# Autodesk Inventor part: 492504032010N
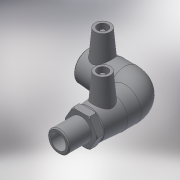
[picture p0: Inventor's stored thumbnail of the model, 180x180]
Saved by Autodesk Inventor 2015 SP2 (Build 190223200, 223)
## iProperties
Created: 2017-06
Part Number: 492504032010N
Material: Generic
Description: PLASSON 90° ELBOW MALE TRANSITION 32 x 1"
Document SubType Name: Modeling
Designer: KIM
Mass: 133.588 g
Surface Area: 417.209 cm^2
Volume: 133.588 cm^3
Density: 1 g/cm^3
Appearance: Default
Author: KIM
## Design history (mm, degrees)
derived "492504.ipt"
feature "Solid1::492504.ipt"
tag "TaggingFeature1"
body "Solid1"
other parameters: "d2" = 44, "d4" = 28, "d5" = 39.6, "d8" = 168 deg, "d10" = 17.6, "d11" = 5.86667, "d29" = 42, "d30" = 15, "d31" = 46.2, "d34" = 5 deg, "d41" = 4, "d42" = 14, "d43" = 0, "d48" = 62, "d49" = 32, "d50" = 27.2, "d51" = 17.6, "d52" = 44, "d54" = 90 deg, "d57" = 32, "d58" = 44, "d59" = 0, "d61" = 90 deg, "d86" = 3, "d87" = 0, "d93" = 0.1, "d94" = 12.5, "d95" = 33.249, "d96" = 23.2743, "d97" = 22, "d99" = 44, "d100" = 45, "d102" = 1.6, "d106" = 0, "d_" = 32, "L_" = 134, "L_1" = 44, "D_" = 22, "A_" = 42, "d_2" = 12, "D_1" = 44, "R_" = 33.249
